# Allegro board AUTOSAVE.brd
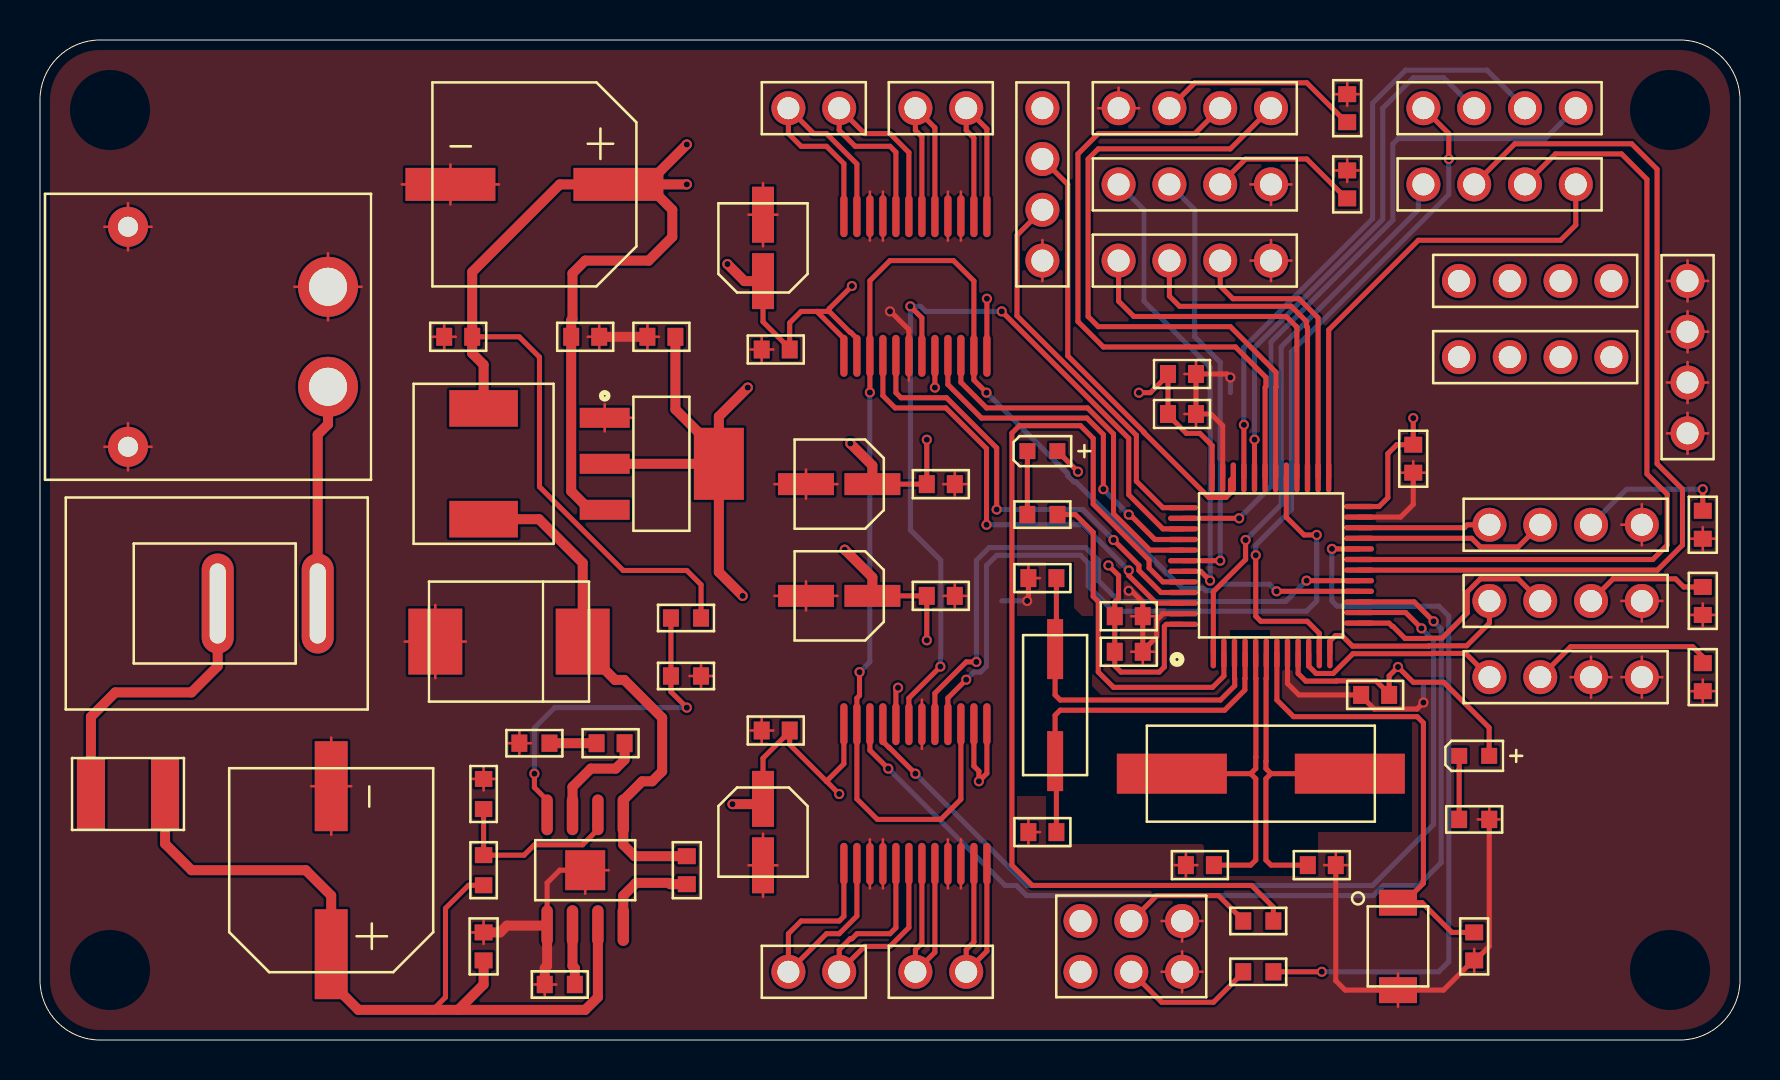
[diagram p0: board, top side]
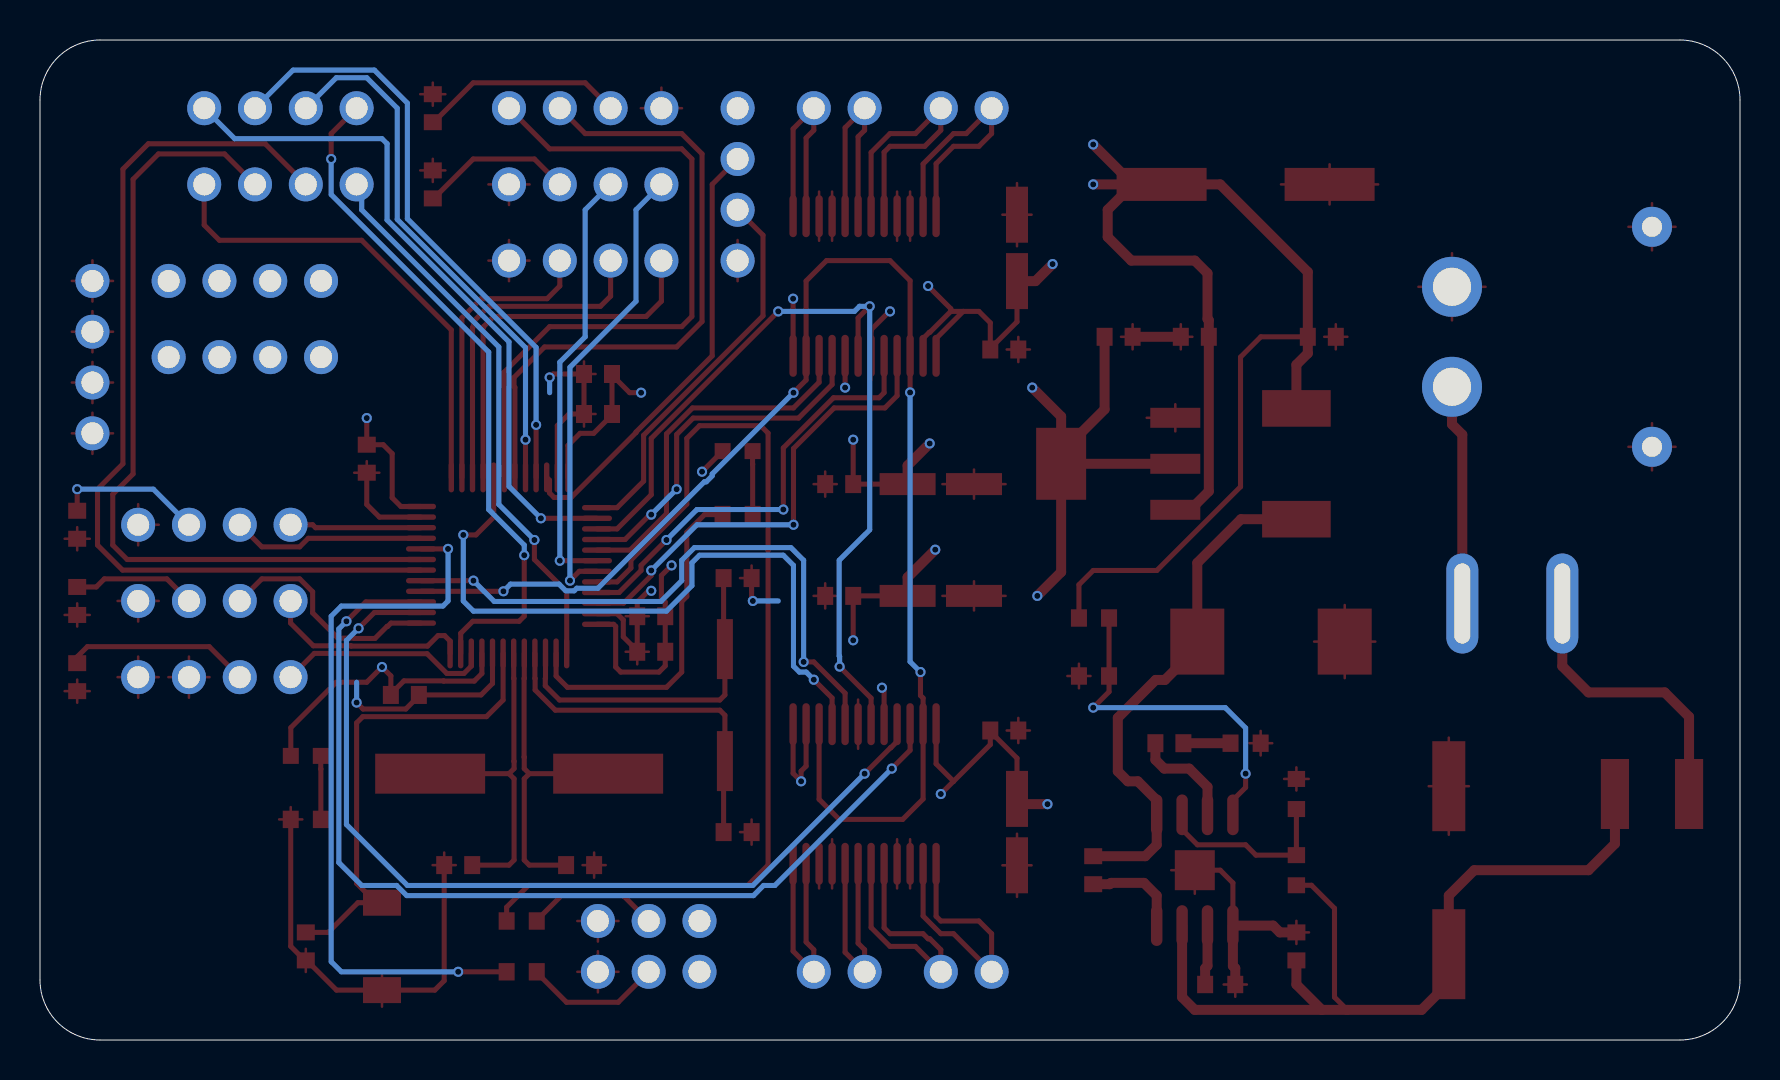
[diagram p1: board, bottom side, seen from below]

Outline 85 x 50 mm; copper layers: TOP, GND, POWER, BOTTOM. Coordinates in mm from the lower left corner of the outline.
Outline path: 0,47 0,3 arc(0.88,0.88) 3,0 82,0 arc(84.12,0.88) 85,3 85,47 arc(84.12,49.12) 82,50 3,50 arc(0.88,49.12) 0,47

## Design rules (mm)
constraint set DEFAULT: min track width 0.127
net group DP1_8MHZ: nets OSC_IN OSC_OUT
net group DP1_32KHZ: nets PC14 PC15

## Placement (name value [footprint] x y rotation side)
C1  22pF,16V  [C0603]  50.12 23.09 0 top
C2  22pF,16V  [C0603]  50.12 10.39 0 top
C3  22pF,16V  [C0603]  57.99 8.74 0 top
C4  22pF,16V  [C0603]  64.09 8.74 180 top
C5  4.7uF,16V  [C0603]  57.1 33.3 180 top
C6  100nF,16V  [C0603]  54.44 19.41 180 top
C7  100nF,16V  [C0603]  71.71 4.68 90 top
C8  100nF,16V  [C0603]  57.1 31.3 180 top
C9  10nF,16V  [C0603]  54.44 21.19 180 top
C10  1uF,16V  [C0603]  66.76 17.25 0 top
C11  100nF,16V  [C0603]  68.66 29.06 90 top
C12  100uF,50V  [C0603]  32.34 8.49 270 top
C13  220uF, 50V  [CP_D10XL10R2]  14.56 8.49 90 top
C14  10uF,50V  [C0603]  22.18 4.68 270 top
C15  22uF,50V  [C0603]  20.91 35.16 180 top
C16  220uF, 50V  [CP_D10XL10R2]  24.72 42.78 180 top
C17  150pF,50V  [C0603]  28.53 14.84 180 top
C18  4.7uF,50V  [C0603]  31.07 35.16 180 top
C19  1uF,50V  [C0603]  27.26 35.16 180 top
C20  100nF,16V  [C0603]  36.78 34.52 0 top
C21  100nF,16V  [C0603]  45.04 27.79 180 top
C22  10uF, 16V  [CP_D4XL54]  36.15 39.61 90 top
C23  10uF, 16V  [CP_D4XL54]  39.96 27.79 180 top
C24  100nF,16V  [C0603]  36.78 15.47 0 top
C25  100nF,16V  [C0603]  45.04 22.21 180 top
C26  10uF, 16V  [CP_D4XL54]  36.15 10.39 270 top
C27  10uF, 16V  [CP_D4XL54]  39.96 22.21 180 top
C28  100nF,16V  [C0603]  65.36 46.59 270 top
C29  100nF,16V  [C0603]  83.14 18.14 90 top
C30  100nF,16V  [C0603]  83.14 21.95 90 top
C31  100nF,16V  [C0603]  65.36 42.78 270 top
C32  100nF,16V  [C0603]  83.14 25.76 90 top
D1  LED  [LED0603]  71.71 14.21 0 top
D2  LED  [LED0603]  50.12 29.45 0 top
D3  SS34  [DO214AB]  23.45 19.92 180 top
F1  SMD1812-150-33 (3A)  [SMD1812]  4.4 12.3 0 top
J1  HEADER 4  [HDR4_P254]  50.12 42.78 90 top
J2  HEADER 3X2  [HDR3X2_P254]  54.56 4.68 0 top
J3  HEADER 4  [HDR4_P254]  72.98 46.59 0 top
J4  HEADER 4  [HDR4_P254]  72.98 42.78 0 top
J5  HDR_3V3  [HDR4_P254]  74.76 37.95 0 top
J6  HDR_5V  [HDR4_P254]  74.76 34.14 0 top
J7  HDR_GND  [HDR4_P254]  82.38 34.14 270 top
J8  HEADER 2  [HDR2_P254]  45.04 46.59 180 top
J9  HEADER 2  [HDR2_P254]  38.69 46.59 180 top
J10  HEADER 2  [HDR2_P254]  38.69 3.41 0 top
J11  HEADER 2  [HDR2_P254]  45.04 3.41 0 top
J12  HDR_USART1  [HDR4_P254]  57.74 46.59 180 top
J13  HDR_USART2  [HDR4_P254]  76.28 21.95 0 top
J14  HDR_SERVO  [HDR4_P254]  76.28 18.14 0 top
J15  HDR_I2C1  [HDR4_P254]  57.74 42.78 180 top
J16  HDR_I2C2  [HDR4_P254]  76.28 25.76 180 top
J17  HDR_SPI2  [HDR4_P254]  57.74 38.97 0 top
L1  10uH,3A  [H0630]  22.18 28.81 90 top
R1  10K  [R0603]  60.91 3.41 180 top
R2  10K  [R0603]  60.91 5.95 0 top
R3  510R  [R0603]  71.71 11.03 0 top
R4  510R  [R0603]  50.12 26.27 0 top
R5  100K  [R0603]  22.18 8.49 270 top
R6  100K  [R0603]  22.18 12.3 270 top
R7  100K  [R0603]  25.99 2.77 0 top
R8  210K 1%  [R0603]  32.3 21.1 180 top
R9  100K  [R0603]  24.72 14.84 0 top
R10  40R2K 1%  [R0603]  32.3 18.2 0 top
SW1  SW_PB_SPST  [SW_PB_4X3]  67.9 4.68 90 top
SW2  -  [KCD11-2P]  11.39 21.82 180 top
U1  STM32F103C8T6  [LQFP_48]  61.55 23.73 0 top
U2  -  [XT30]  4.4 35.16 90 top
U3  MP1584EN  [SOIC-8-EP]  27.26 8.49 180 top
U4  LDL1117_33R  [SOT223]  31.07 28.81 180 top
U5  TB6612FNG  [SSOP24]  43.77 37.7 180 top
U6  TB6612FNG  [SSOP24]  43.77 12.3 0 top
Y1  32.768kHz  [SMD_32KHZ]  50.76 16.74 90 top
Y2  8MHz  [SMD_8MHZ]  61.04 13.32 180 top

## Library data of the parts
C1-C12 C14 C15 C17-C21 C24 C25 C28-C32 = CAP NP
C13 C16 C22 C23 C26 C27 = CAP POL
D1 D2 = LED
D3 = DIODE
F1 = FUSE
J1 J3-J7 J12-J17 = HEADER 4
J2 = HEADER 3X2
J8-J11 = HEADER 2
L1 = INDUCTOR
R1-R10 = R2
SW1 = SW_PB_SPST
SW2 = SW SPST
U1 = STM32F103C8T6
U2 = XT30
U3 = MP1584EN
U4 = LDL1117_33R
U5 U6 = TB6612FNG
Y1 Y2 = CRYSTAL

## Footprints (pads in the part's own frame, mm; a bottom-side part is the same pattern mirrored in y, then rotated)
C0603
  rect 0.8x0.9 smd: 1(-0.7,0) 2(0.7,0)
CP_D4XL54
  rect 2.8x1.1 smd: 1(-1.66,0) 2(1.66,0)
CP_D10XL10R2
  rect 4.5x1.65 smd: 1(-4.2,0) 2(4.2,0)
DO214AB
  rect 2.7x3.3 smd: 1(-3.686,0) 2(3.686,0)
H0630
  rect 1.83x3.43 smd: 1(-2.77,0) 2(2.77,0)
HDR2_P254
  round 1.7 hole 1.1: 1(-1.27,0) 2(1.27,0)
HDR3X2_P254
  round 1.7 hole 1.1: 1(-2.54,1.27) 2(-2.54,-1.27) 3(0,1.27) 4(0,-1.27) 5(2.54,1.27) 6(2.54,-1.27)
HDR4_P254
  round 1.7 hole 1.1: 1(-3.81,0) 2(-1.27,0) 3(1.27,0) 4(3.81,0)
KCD11-2P
  oval 1.6x5 hole 0.8x4 unplated: (-2.5,0) (2.5,0)
LED0603
  rect 0.8x0.8 smd: 1(-0.749,0) 2(0.749,0)
LQFP_48
  oval 0.27x1.5 smd: 1(-2.885,-4.4) 2(-2.355,-4.4) 3(-1.825,-4.4) 4(-1.295,-4.4) 5(-0.765,-4.4) 6(-0.235,-4.4) 7(0.295,-4.4) 8(0.825,-4.4) 9(1.355,-4.4) 10(1.885,-4.4) 11(2.415,-4.4) 12(2.945,-4.4) 25(2.885,4.4) 26(2.355,4.4) 27(1.825,4.4) 28(1.295,4.4) 29(0.765,4.4) 30(0.235,4.4) 31(-0.295,4.4) 32(-0.825,4.4) 33(-1.355,4.4) 34(-1.885,4.4) 35(-2.415,4.4) 36(-2.945,4.4)
  oval 1.5x0.27 smd: 13(4.4,-2.885) 14(4.4,-2.355) 15(4.4,-1.825) 16(4.4,-1.295) 17(4.4,-0.765) 18(4.4,-0.235) 19(4.4,0.295) 20(4.4,0.825) 21(4.4,1.355) 22(4.4,1.885) 23(4.4,2.415) 24(4.4,2.945) 37(-4.4,2.885) 38(-4.4,2.355) 39(-4.4,1.825) 40(-4.4,1.295) 41(-4.4,0.765) 42(-4.4,0.235) 43(-4.4,-0.295) 44(-4.4,-0.825) 45(-4.4,-1.355) 46(-4.4,-1.885) 47(-4.4,-2.415) 48(-4.4,-2.945)
R0603
  rect 0.8x0.87 smd: 1(-0.753,0) 2(0.753,0)
SMD1812
  rect 1.407x3.499 smd: 1(-1.853,0) 2(1.853,0)
SMD_8MHZ
  rect 5.5x2 smd: 1(-4.45,0) 2(4.45,0)
SMD_32KHZ
  rect 3x0.8 smd: 1(-2.8,0) 2(2.8,0)
SOIC-8-EP
  oval 0.574x2.038 smd: 1(-1.905,-2.769) 2(-0.635,-2.769) 3(0.635,-2.769) 4(1.905,-2.769) 5(1.905,2.769) 6(0.635,2.769) 7(-0.635,2.769) 8(-1.905,2.769)
  rect 2x2 smd: 9(0,0)
SOT223
  rect 2.5x1 smd: 1(2.835,-2.3) 2(2.835,0) 3(2.835,2.3)
  rect 2.5x3.6 smd: 4(-2.873,0)
SSOP24
  oval 0.37x2.1 smd: 1(-3.575,-3.491) 2(-2.925,-3.491) 3(-2.275,-3.491) 4(-1.625,-3.491) 5(-0.975,-3.491) 6(-0.325,-3.491) 7(0.325,-3.491) 8(0.975,-3.491) 9(1.625,-3.491) 10(2.275,-3.491) 11(2.925,-3.491) 12(3.575,-3.491) 13(3.575,3.491) 14(2.925,3.491) 15(2.275,3.491) 16(1.625,3.491) 17(0.975,3.491) 18(0.325,3.491) 19(-0.325,3.491) 20(-0.975,3.491) 21(-1.625,3.491) 22(-2.275,3.491) 23(-2.925,3.491) 24(-3.575,3.491)
SW_PB_4X3
  rect 1.3x1.9 smd: 1(-2.185,0) 2(2.185,0)
XT30
  round 3 hole 1.9: 1(2.5,-10) 2(-2.5,-10)
  round 2 hole 1: 3(5.5,0) 4(-5.5,0)

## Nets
GND: C1.1 C2.1 C3.1 C4.1 C5.1 C6.1 C7.1 C8.1 C9.1 C10.1 C11.1 C13.2 C14.1 C15.2 C16.2 C18.2 C19.1 C20.1 C21.1 C22.2 C23.2 C24.1 C25.1 C26.2 C27.2 C28.1 C29.1 C30.1 C31.1 C32.1 D3.2 J1.1 J2.5 J2.6 J7.1 J7.2 J7.3 J7.4 J12.4 J13.4 J14.3 J14.4 J15.1 J16.1 J17.4 R3.2 R6.1 R7.1 R9.1 R10.2 SW1.1 U1.8 U1.23 U1.35 U1.47(VSS_3) U2.1 U2.3 U2.4 U3.5 U3.9 U4.1 U5.3 U5.4 U5.9 U5.10 U5.18 U6.3 U6.4 U6.9 U6.10 U6.18
VBAT: J4.1 U1.1
VCC3V3: C5.2 C6.2 C8.2 C9.2 C10.2 C11.2 C18.1 C30.2 C31.2 C32.2 D1.2 D2.2 J1.4 J2.1 J2.2 J5.1 J5.2 J5.3 J5.4 J13.3 J15.2 J16.2 U1.9 U1.24 U1.36 U1.48 U4.2 U4.4(VOUT2)
VCC5V: C15.1 C16.1 C19.2 C20.2 C21.2 C22.1 C23.1 C24.2 C25.2 C26.1 C27.1 C28.2 C29.2 J6.1 J6.2 J6.3 J6.4 J12.3 J14.2 L1.2 R8.1 U4.3 U5.13 U5.14(VM3) U5.20 U5.24 U6.13 U6.14(VM3) U6.20 U6.24
VIN_BAT: C13.1 C14.2 F1.2 R5.2 U3.7(VIN)
BOOT0: R2.2 U1.44
BOOT1: R1.1 U1.20
I2C1_SCL: J15.3 U1.42
I2C1_SDA: J15.4 U1.43
I2C2_SCL: J16.3 U1.21
I2C2_SDA: J16.4 U1.22
MOTORIC1_AIN1: U1.40 U5.21
MOTORIC1_AIN2: U1.41 U5.22
MOTORIC1_BIN1: U1.45 U5.17
MOTORIC1_BIN2: U1.46 U5.16
MOTORIC2_AIN1: U1.14 U6.21
MOTORIC2_AIN2: U1.15 U6.22
MOTORIC2_BIN1: U1.17 U6.17
MOTORIC2_BIN2: U1.29 U6.16
MOTORIC_STBY: U1.39 U5.19 U6.19
OSC_IN: C3.2 U1.5 Y2.2
OSC_OUT: C4.2 U1.6 Y2.1
PA1: J3.1 U1.11
PA11: J3.2 U1.32
PA12: J3.3 U1.33
PA15: J3.4 U1.38
PB0: J4.2 U1.18
PB1: J4.3 U1.19
PB12: J4.4 U1.25
PC13: R4.2 U1.2
PC14: C1.2 U1.3 Y1.2
PC15: C2.2 U1.4 Y1.1
RESET: C7.2 SW1.2 U1.7
SPI2_MISO: J17.2 U1.27
SPI2_MOSI: J17.1 U1.28
SPI2_SCK: J17.3 U1.26
SWCLK: J1.2 U1.37
SWDIO: J1.3 U1.34
TIM2_PWM: J14.1 U1.10
TIM3_PWM: U1.16 U5.15 U5.23 U6.15 U6.23
USART1_RX: J12.2 U1.31
USART1_TX: J12.1 U1.30
USART2_RX: J13.2 U1.13
USART2_TX: J13.1 U1.12
N13546: J8.1 U5.1 U5.2
N13563: J8.2 U5.5 U5.6
N13598: J9.1 U5.7 U5.8
N13619: J9.2 U5.11 U5.12
N15223: J10.1 U6.1 U6.2
N15263: J10.2 U6.5 U6.6
N15407: J11.1 U6.7 U6.8
N15519: J11.2 U6.11 U6.12
N31972: C12.2 U3.8
N31979: C12.1 D3.1(K) L1.1 U3.1
N32592: R7.2 U3.6
N32821: R5.1 R6.2 U3.2
N35796: C17.1 U3.3
N36210: C17.2 R9.2
N38494: R8.2 R10.1 U3.4
N053341: J2.4 R1.2
N053344: J2.3 R2.1
N066431: D1.1(CATHODE) R3.1
N066591: D2.1(CATHODE) R4.1
N113201: U2.2
N288331: F1.1

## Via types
v1: diameter 0.508, hole 0.305, TOP to BOTTOM, 60 vias

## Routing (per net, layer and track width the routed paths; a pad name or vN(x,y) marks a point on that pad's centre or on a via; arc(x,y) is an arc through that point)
GND: length 334.8
  TOP w0.127: 82.38,34.39 J7.2 ; J7.2 83.41,35.41 ; J7.2 82.38,36.44 ; J7.2 81.35,35.41 ; 68.03,28.36 C11.1 ; C11.1 69.29,28.36 ; C11.1 68.66,28.94 ; 45.74,21.58 C25.1 ; C25.1 46.32,22.21 ; C25.1 45.74,22.83 ; C25.1 45.16,22.21 ; 22.18,4.8 C14.1 ; C14.1 22.18,5.96 ; C14.1 21.55,5.38 ; U4.1 28.23,31.79 ; U4.1 28.23,30.43 ; U4.1 29.66,31.11 ; U2.1 16.08,37.66 ; U2.1 14.4,35.98 ; U2.1 14.4,39.34 ; U2.1 12.72,37.66 ; 41.49,42.42 U5.10 41.49,39.96 ; C4.1 64.79,9.37 ; C4.1 65.37,8.74 ; C4.1 64.21,8.74 ; 80.09,17.11 J14.4 ; J14.4 81.12,18.14 ; J14.4 80.09,19.17 ; J14.4 79.06,18.14 ; 27.96,34.53 C19.1 ; C19.1 27.96,35.79 ; C19.1 27.38,35.16 ; 43.45,32.98 U5.18 ; 45.16,27.79 C21.1 ; C21.1 45.74,28.42 ; C21.1 45.74,27.17 ; C21.1 46.32,27.79 ; J17.4 61.55,40 ; J17.4 62.58,38.97 ; J17.4 61.55,37.94 ; J17.4 60.52,38.97 ; C22.2 36.88,41.27 ; C22.2 36.15,42.84 ; C22.2 36.15,39.69 ; C22.2 35.42,41.27 ; 57.8,30.67 C8.1 57.22,31.3 ; C32.1 83.77,25.06 ; C32.1 83.14,24.48 ; C32.1 82.51,25.06 ; C32.1 83.14,25.64 ; 56.72,8.74 C3.1 ; C3.1 57.29,8.12 ; C3.1 57.29,9.37 ; C3.1 57.87,8.74 ; 4.4,28.48 U2.4 ; U2.4 5.58,29.66 ; U2.4 4.4,30.84 ; U2.4 3.22,29.66 ; 4.4,39.48 U2.3 ; U2.3 5.58,40.66 ; U2.3 3.22,40.66 ; U2.3 4.4,41.84 ; C29.1 83.77,17.44 ; C29.1 82.51,17.44 ; C29.1 83.14,16.86 ; C29.1 83.14,18.02 ; 41.49,10.04 U6.3 41.49,7.58 ; 25.24,2.16 R7.1 ; R7.1 25.82,2.77 ; R7.1 24.66,2.77 ; C18.2 30.37,35.79 ; C18.2 30.37,34.53 ; C18.2 30.95,35.16 ; 32.48,18.2 R10.2 ; R10.2 33.05,18.81 ; R10.2 33.63,18.2 ; R10.2 33.05,17.59 ; 42.15,39.96 42.15,42.42 ; 56.08,5.95 J2.5 ; J2.5 58.13,5.95 ; J2.5 57.11,4.92 ; 81.35,37.95 J7.1 ; J7.1 82.38,36.93 ; J7.1 83.41,37.95 ; J7.1 82.38,38.98 ; 42.15,10.04 U6.4 42.15,7.58 ; 60.52,42.78 J15.1 ; J15.1 61.55,41.75 ; J15.1 62.58,42.78 ; 35.42,8.73 C26.2 ; C26.2 36.15,7.16 ; C26.2 36.88,8.73 ; C26.2 36.15,10.31 ; 81.35,32.87 J7.3 ; J7.3 83.41,32.87 ; J7.3 82.38,31.85 ; J7.3 82.38,33.9 ; 79.06,21.95 J13.4 ; J13.4 81.12,21.95 ; J13.4 80.09,20.92 ; C13.2 15.56,12.69 ; C13.2 14.56,10.26 ; C13.2 13.56,12.69 ; C13.2 14.56,15.12 ; 64.73,43.48 C31.1 ; C31.1 65.36,44.06 ; C31.1 65.36,42.9 ; C31.1 65.99,43.48 ; 35.51,15.47 C24.1 ; C24.1 36.66,15.47 ; C24.1 36.09,14.85 ; C24.1 36.09,16.1 ; J16.1 80.09,26.79 ; J16.1 80.09,24.73 ; J16.1 79.06,25.76 ; R6.1 22.18,13.63 ; R6.1 22.18,12.47 ; R6.1 22.79,13.05 ; R6.1 21.57,13.05 ; 49.42,23.72 C1.1 50,23.09 ; 45.4,39.96 U5.4 45.4,42.42 ; 55.72,21.19 C9.1 54.56,21.19 ; C15.2 20.21,35.79 ; C15.2 19.63,35.16 ; C15.2 20.79,35.16 ; C15.2 20.21,34.53 ; 57.8,33.93 C5.1 57.22,33.3 ; 52.9,46.59 J12.4 ; J12.4 53.93,47.62 ; J12.4 54.96,46.59 ; C6.1 55.72,19.41 ; C6.1 55.14,18.78 ; C6.1 54.56,19.41 ; J7.4 83.41,30.33 ; J7.4 81.35,30.33 ; J7.4 82.38,29.31 ; J7.4 82.38,31.36 ; 83.14,20.67 C30.1 ; C30.1 83.77,21.25 ; C30.1 83.14,21.83 ; C30.1 82.51,21.25 ; 36.72,27.79 C23.2 ; C23.2 38.3,27.07 ; C23.2 39.88,27.79 ; C23.2 38.3,28.52 ; R9.1 24.55,14.84 ; R9.1 23.39,14.84 ; R9.1 23.97,15.45 ; R9.1 23.97,14.23 ; R3.2 72.46,11.64 ; R3.2 71.89,11.03 ; R3.2 73.04,11.03 ; C2.1 50,10.39 ; C2.1 49.42,9.77 ; C2.1 49.42,11.02 ; 50.12,40 J1.1 50.12,37.94 ; 46.05,7.58 U6.10 46.05,10.04 ; C20.1 36.09,35.15 ; C20.1 35.51,34.52 ; C20.1 36.66,34.52 ; C20.1 36.09,33.9 ; 77.55,17.11 J14.3 ; J14.3 77.55,19.17 ; J14.3 76.52,18.14 ; J14.3 78.58,18.14 ; 46.05,42.42 46.05,39.96 ; 45.4,10.04 U6.9 45.4,7.58 ; 67.9,3.32 SW1.1 67.9,1.67 ; 71.71,3.4 C7.1 71.71,4.56 ; 57.11,2.38 J2.6 ; J2.6 57.11,4.44 ; J2.6 56.08,3.41 ; J2.6 58.13,3.41 ; 18.09,42.78 C16.2 ; C16.2 20.52,43.78 ; C16.2 20.52,41.78 ; C16.2 22.95,42.78 ; 64.73,47.29 C28.1 ; C28.1 65.36,47.87 ; C28.1 65.99,47.29 ; C28.1 65.36,46.71 ; 44.09,14.56 U6.18 44.09,17.02 ; 27.26,7.31 U3.9 28.44,8.49 ; 18.24,19.92 D3.2 ; D3.2 19.76,18.09 ; D3.2 19.76,21.75 ; D3.2 21.29,19.92 ; C27.2 38.3,22.93 ; C27.2 39.88,22.21 ; C27.2 38.3,21.48 ; C27.2 36.72,22.21
  TOP w0.254: v1(42.5,36.43) 42.53,36.43 43.45,35.51 U5.18 ; U1.23 68.03,26.14 68.66,26.78 C11.1 ; v1(49.36,21.95) 49.42,22.01 C1.1 ; U3.9 25.99,8.49 25.36,7.86 U3.5 ; 55.14,19.46 55.84,20.16 55.84,21 56.15,21.32 U1.47 ; 55.14,19.46 C6.1 ; 55.14,19.46 C9.1 55.14,21.89 54.57,22.46 v1(54.44,22.46) ; v1(69.17,16.87) 68.85,16.55 66.71,16.55 66.06,17.2 66.06,17.25 62.95,17.25 62.38,17.82 U1.8 ; R3.2 72.46,4.68 71.76,3.98 C7.1 71.66,3.98 70.17,2.5 SW1.1 65.26,2.5 64.79,2.96 C4.1 ; U1.35 59.14,30.72 58.55,31.3 C8.1 C5.1 59.35,33.3 v1(59.52,33.13)
  TOP w0.5: R7.1 25.24,3.59 25.36,3.7 U3.5 23.35,5.72 23.01,5.38 C14.1 ; C19.1 C18.2
  GND w0.127: 81.35,30.33 J7.4 ; J7.4 83.41,30.33 ; J7.4 82.38,29.31 ; J7.4 82.38,31.36 ; 4.4,39.48 U2.3 ; U2.3 3.22,40.66 ; U2.3 4.4,41.84 ; U2.3 5.58,40.66 ; 81.35,35.41 J7.2 ; J7.2 82.38,36.44 ; J7.2 83.41,35.41 ; J7.2 82.38,34.39 ; U2.4 4.4,30.84 ; U2.4 4.4,28.48 ; U2.4 3.22,29.66 ; U2.4 5.58,29.66 ; J7.3 82.38,33.9 ; J7.3 83.41,32.87 ; J7.3 82.38,31.85 ; J7.3 81.35,32.87 ; J12.4 54.96,46.59 ; J12.4 52.9,46.59 ; J12.4 53.93,45.56 ; J12.4 53.93,47.62 ; 14.4,35.98 U2.1 ; U2.1 14.4,39.34 ; U2.1 12.72,37.66 ; U2.1 16.08,37.66 ; 49.09,38.97 J1.1 ; J1.1 50.12,37.94 ; J1.1 50.12,40 ; J1.1 51.15,38.97 ; J2.6 58.13,3.41 ; J2.6 57.11,4.44 ; J2.6 56.08,3.41 ; J2.6 57.11,2.38 ; 56.08,5.95 J2.5 ; J2.5 58.13,5.95 ; J2.5 57.11,4.92 ; J2.5 57.11,6.98 ; 76.52,18.14 J14.3 ; J14.3 77.55,19.17 ; J14.3 78.58,18.14 ; J14.3 77.55,17.11 ; J7.1 83.41,37.95 ; J7.1 82.38,38.98 ; J7.1 82.38,36.93 ; J7.1 81.35,37.95 ; 61.55,41.75 J15.1 ; J15.1 62.58,42.78 ; J15.1 61.55,43.81 ; J15.1 60.52,42.78 ; 60.52,38.97 J17.4 ; J17.4 61.55,37.94 ; J17.4 61.55,40 ; J17.4 62.58,38.97 ; J14.4 80.09,19.17 ; J14.4 79.06,18.14 ; J14.4 80.09,17.11 ; J14.4 81.12,18.14 ; 79.06,25.76 J16.1 ; J16.1 80.09,26.79 ; J16.1 80.09,24.73 ; J16.1 81.12,25.76 ; 80.09,20.92 J13.4 ; J13.4 80.09,22.98 ; J13.4 79.06,21.95 ; J13.4 81.12,21.95
  GND w0.254: v1(42.5,36.43) 42.5,37.19
  BOTTOM w0.254: v1(49.36,21.95) 48.09,21.95 ; v1(59.52,33.13) 59.52,32.37 ; v1(69.17,16.87) 69.17,17.89
VBAT: length 27.8
  TOP w0.254: v1(60.28,25) 60.28,24.03 58.66,22.41 U1.1
  BOTTOM w0.254: J4.1 68.92,42.53 68.92,41.51 62.06,34.65 62.06,26.78 v1(60.28,25)
VCC3V3: length 256.2
  TOP w0.254: D2.2 v1(51.9,28.42) ; U1.48 56.32,20.79 56.22,20.68 56.22,18.65 55.96,18.4 54.05,18.4 53.74,18.71 C6.2 C9.2 53.74,21.89 53.93,22.09 53.93,23.22 v1(53.42,23.73) ; v1(54.95,32.37) 55.52,32.37 56.4,33.25 ; C10.2 67.46,17.3 ; 67.46,17.3 67.46,18.21 v1(67.9,18.65) 68.66,17.89 70.19,17.89 72.46,15.62 D1.2 ; 67.46,17.3 66.8,17.96 64.83,17.96 64.81,17.95 63.29,17.95 62.91,18.33 U1.9 ; 56.4,33.25 C5.2 ; 56.4,33.25 C8.2 56.4,31.25 57.32,30.33 57.99,30.33 58.61,29.72 U1.36 ; C32.2 v1(83.14,27.54) ; v1(68.66,31.1) C11.2 67.84,29.76 67.39,29.32 67.39,27.11 66.95,26.68 65.95,26.68 ; J13.3 78.66,23.06 81.78,23.06 82.19,22.65 C30.2 ; C31.2 65.31,42.08 63.34,44.05 60.28,44.05 J15.2
  TOP w0.5: v1(35.39,32.62) 33.94,31.18 33.94,29.36 ; U4.2 U4.4 ; U4.4 33.94,29.36 ; U4.4 33.94,23.4 v1(35.13,22.21) ; 33.94,29.36 31.77,31.53 C18.1
  POWER w0.254: 54.18,33.89 54.95,33.13 v1(54.95,32.37) ; 49.87,33.89 51.9,31.86 v1(51.9,28.42) ; 66.63,33.89 68.66,31.86 v1(68.66,31.1)
  POWER w0.5: J5.4 J5.3 J5.2 J5.1 66.88,33.89 ; 49.1,33.89 51.64,36.43 51.64,45.07 J1.4 ; 49.1,33.89 36.66,33.89 v1(35.39,32.62) ; 49.1,33.89 62.31,33.89 ; 66.88,33.89 68.41,33.89 70.44,31.86 76.28,31.86 77.55,30.59 J16.2 J13.3 75.77,20.17 72.22,20.17 70.69,18.65 v1(67.9,18.65) ; 66.88,33.89 62.31,33.89 ; 62.31,33.89 63.84,35.41 63.84,40.24 63.33,40.75 61.04,40.75 J15.2 ; v1(53.42,23.73) 52.15,25 42.68,25 41.03,23.35 36.28,23.35 v1(35.13,22.21) 38.44,18.9 38.44,7.73 39.2,6.97 51.01,6.97 J2.1 J2.2
  BOTTOM w0.254: J16.2 79.33,27.54 v1(83.14,27.54)
VCC5V: length 312.6
  TOP w0.254: 38.84,36.43 38.05,36.43 37.48,35.86 37.48,34.58 ; 38.84,36.43 40.2,35.07 40.2,34.21 ; 38.84,36.43 39.46,36.43 ; 37.48,15.43 37.48,14.77 39.32,12.94 ; 37.48,15.43 C24.2 ; 37.48,15.43 36.15,14.09 C26.1 ; v1(44.34,30.02) C21.2 C23.1 ; U6.20 42.8,17.51 v1(42.9,17.61) ; C22.1 36.15,35.91 37.48,34.58 ; J14.2 76.54,19.67 82.63,19.67 83.14,19.16 C29.2 ; U5.14 40.84,35.07 40.53,35.38 40.51,35.38 39.46,36.43 ; 39.32,12.94 39.33,12.94 v1(39.96,12.3) ; 39.32,12.94 40.2,13.81 U6.24 ; C15.1 23.96,35.16 24.97,34.14 24.97,27.66 29.16,23.48 32.34,23.48 33.05,22.76 R8.1 ; C28.2 65.31,45.89 63.34,47.86 57.74,47.86 J12.3 ; v1(44.74,32.62) U5.20 ; v1(47.34,37.06) 47.34,34.21 ; U6.14 46.7,13.69 46.95,13.44 v1(46.95,12.94) 47.34,13.34 47.34,15.79 ; v1(44.34,19.98) C25.2 C27.1 ; 37.48,34.58 C20.2 ; 39.46,36.43 39.46,36.56 v1(40.59,37.7)
  TOP w0.5: U4.3 27.48,26.51 26.56,27.43 C19.2 26.56,35.99 26.62,36.05 26.62,38.34 27.26,38.97 30.44,38.97 31.62,40.15 31.62,41.51 30.34,42.78 ; 30.34,42.78 v1(32.34,42.78) ; 30.34,42.78 v1(32.34,44.77) ; 30.34,42.78 C16.1 25.99,42.78 21.61,38.4 C15.1 21.61,34.33 22.18,33.76 L1.2 ; C23.1 41.62,28.72 v1(40.52,29.83) ; v1(34.37,38.8) 35.22,37.95 C22.1 ; C27.1 41.62,23.13 v1(40.24,24.52) ; v1(34.63,11.79) 35.89,11.79 C26.1
  POWER w0.254: v1(46.95,12.94) 46.31,12.3 v1(39.96,12.3) ; v1(47.34,37.06) 46.71,37.7 v1(40.59,37.7) ; v1(44.74,32.62) 44.34,32.22 v1(44.34,30.02) ; v1(42.9,17.61) 44.34,19.05 v1(44.34,19.98)
  POWER w0.5: v1(34.37,38.8) 34.29,38.8 33.36,39.73 ; 33.36,26.02 34.86,24.52 v1(40.24,24.52) ; 33.36,26.02 33.36,32.37 ; 33.36,26.02 33.36,13.06 v1(34.63,11.79) ; 79.84,35.41 79.84,30.59 81.87,28.56 81.87,16.87 80.85,15.86 77.3,15.86 J14.2 ; 79.84,35.41 J6.4 J6.3 J6.2 J6.1 ; 79.84,35.41 80.09,35.67 80.09,39.99 78.82,41.26 78.82,46.84 77.3,48.37 54.7,48.37 ; 33.36,32.37 35.9,29.83 v1(40.52,29.83) ; 33.36,32.37 33.36,39.73 ; v1(32.34,44.77) 35.93,48.37 54.7,48.37 ; 54.7,48.37 55.2,47.87 55.2,47.86 J12.3 ; v1(32.34,42.78) 33.36,41.76 33.36,39.73
VIN_BAT: length 44.7
  TOP w0.254: 19.64,1.5 20.27,2.14 20.27,6.59 21.43,7.74 R5.2
  TOP w0.5: 20.91,1.5 15.92,1.5 14.56,2.86 C13.1 14.56,7.22 13.29,8.49 7.58,8.49 6.25,9.81 F1.2 ; 20.91,1.5 27.26,1.5 27.89,2.14 U3.7 ; 20.91,1.5 22.18,2.77 C14.2
BOOT0: length 50.3
  TOP w0.254: R2.2 61.67,6.64 60.58,7.73 49.61,7.73 48.6,8.74 48.6,30.34 48.97,30.71 52.02,30.71 52.66,30.08 52.66,26.79 55.45,24 55.45,23.6 56.15,22.91 57.15,22.91
BOOT1: length 36.4
  TOP w0.254: R1.1 v1(64.09,3.41) ; v1(64.6,24.55) 65.95,24.55
  BOTTOM w0.254: v1(64.6,24.55) 64.6,21.95 64.85,21.7 69.93,21.7 70.44,21.19 70.44,3.92 69.93,3.41 v1(64.09,3.41)
I2C1_SCL: length 21.7
  TOP w0.254: U1.42 v1(59.01,23.96)
  BOTTOM w0.254: v1(59.01,23.96) 59.01,33.89 57.74,35.16 57.74,41.51 J15.3
I2C1_SDA: length 23.3
  TOP w0.254: U1.43 58.03,23.43 v1(58.5,22.97)
  BOTTOM w0.254: J15.4 55.2,41.51 55.2,36.94 58.5,33.64 v1(58.5,22.97)
I2C2_SCL: length 9.7
  TOP w0.254: U1.21 71.59,25.09 72.01,24.66 73.91,24.66 J16.3
I2C2_SDA: length 6.6
  TOP w0.254: U1.22 71.22,25.61 71.37,25.76 J16.4
MOTORIC1_AIN1: length 18
  TOP w0.254: 45.4,34.21 45.4,32.77 47.07,31.1 52.34,31.1 53.17,30.27 v1(53.17,27.54) ; v1(54.44,26.27) 54.56,26.14 54.63,26.14 55.74,25.02 U1.40
  BOTTOM w0.254: v1(53.17,27.54) v1(54.44,26.27)
MOTORIC1_AIN2: length 18.2
  TOP w0.254: U5.22 46.05,32.88 47.33,31.6 52.38,31.6 53.68,30.3 53.68,26.31 55.49,24.5 U1.41
MOTORIC1_BIN1: length 22.3
  TOP w0.254: v1(47.83,26.52) 47.83,29.6 45.32,32.11 43.05,32.11 42.8,32.37 42.8,34.21 ; U1.45 56.05,22.38 54.95,23.48 54.95,23.73 v1(53.68,25)
  BOTTOM w0.254: v1(47.83,26.52) 52.15,26.52 v1(53.68,25)
MOTORIC1_BIN2: length 23.7
  TOP w0.254: U5.16 42.15,32.21 42.75,31.6 45.29,31.6 47.33,29.57 v1(47.33,25.76) ; U1.46 55.81,21.84 54.44,23.22 v1(54.44,23.48)
  BOTTOM w0.254: v1(54.44,23.48) 52.15,25.76 v1(47.33,25.76)
MOTORIC2_AIN1: length 46.2
  TOP w0.254: v1(69.07,20.58) 68.28,21.38 U1.14 ; v1(43.77,13.32) 42.47,14.62 42.46,14.62 42.15,14.93 U6.21
  BOTTOM w0.254: v1(69.07,20.58) 69.68,19.98 69.68,10.78 66.63,7.73 49.36,7.73 v1(43.77,13.32)
MOTORIC2_AIN2: length 49.9
  TOP w0.254: 65.95,21.91 68.71,21.91 v1(69.68,20.94) ; v1(42.41,13.57) 41.49,14.49 U6.22
  BOTTOM w0.254: v1(69.68,20.94) 70.06,20.55 70.06,8.87 68.92,7.73 67.17,7.73 66.66,7.22 49.33,7.22 48.82,7.73 48.25,7.73 v1(42.41,13.57)
MOTORIC2_BIN1: length 30.9
  TOP w0.254: U6.17 44.74,17.34 46.31,18.9 v1(46.82,18.9) ; v1(63.33,22.97) 63.84,22.97 63.84,22.96 U1.17
  BOTTOM w0.254: v1(46.82,18.9) 46.82,23.98 47.45,24.62 52.28,24.62 52.91,23.98 52.91,22.97 53.96,21.93 62.29,21.93 v1(63.33,22.97)
MOTORIC2_BIN2: length 34.9
  TOP w0.254: v1(46.31,18.02) 45.4,17.1 U6.16 ; U1.29 62.31,26.14 63.2,25.25 v1(63.84,25.25)
  BOTTOM w0.254: v1(63.84,25.25) 63.84,21.95 63.33,21.44 53.68,21.44 52.41,22.71 52.41,23.86 52.02,24.24 47.83,24.24 47.33,23.73 47.33,18.69 47.03,18.4 46.69,18.4 v1(46.31,18.02)
MOTORIC_STBY: length 44.8
  TOP w0.254: 43.45,15.79 43.45,17.09 v1(45.02,18.67) ; v1(48.09,36.43) 54.44,30.08 54.44,27.26 56.15,25.55 57.15,25.55 ; v1(43.52,36.68) 44.09,36.11 44.09,34.21
  BOTTOM w0.254: v1(45.02,18.67) 45.02,19.18 45.04,19.2 45.04,23.98 43.52,25.51 v1(43.52,36.68) 44.02,36.68 44.28,36.43 v1(48.09,36.43)
OSC_IN: length 16.7
  TOP w0.254: 60.53,13.32 60.79,13.57 60.79,14.14 60.8,14.15 60.8,18.07 60.78,18.08 U1.5 ; 60.53,13.32 60.79,13.06 60.79,9 60.53,8.74 C3.2 ; 60.53,13.32 Y2.2
OSC_OUT: length 16.7
  TOP w0.254: 61.55,13.32 Y2.1 ; 61.55,13.32 61.3,13.06 61.3,9 61.55,8.74 C4.2 ; 61.55,13.32 61.3,13.57 61.3,13.93 61.3,13.94 61.3,18.07 61.31,18.08 U1.6
PA1: length 34.5
  TOP w0.254: v1(70.44,44.05) 70.44,45.32 J3.1 ; U1.11 63.97,20.33 63.36,20.94 61.04,20.94 60.79,21.19 v1(60.79,24.24)
  BOTTOM w0.254: v1(60.79,24.24) 60.79,24.75 62.57,26.52 62.57,34.4 70.44,42.27 v1(70.44,44.05)
PA11: length 27
  TOP w0.254: U1.32 v1(60.73,30.02)
  BOTTOM w0.254: v1(60.73,30.02) 60.73,34.62 67.14,41.03 67.14,46.59 68.66,48.11 70.19,48.11 J3.2
PA12: length 30.5
  TOP w0.254: U1.33 v1(60.2,30.76)
  BOTTOM w0.254: v1(60.2,30.76) 60.2,34.63 66.63,41.06 66.63,46.84 68.28,48.5 72.34,48.5 J3.3
PA15: length 34.6
  TOP w0.254: U1.38 v1(59.96,26.09)
  BOTTOM w0.254: J3.4 75.27,45.07 67.9,45.07 67.65,44.81 67.65,41 61.55,34.91 61.55,27.68 v1(59.96,26.09)
PB0: length 46.5
  TOP w0.254: J4.2 73.74,44.81 79.58,44.81 80.85,43.54 80.85,28.81 82.12,27.54 82.12,24.75 80.87,23.5 U1.18
PB1: length 41.7
  TOP w0.254: J4.3 75.77,44.3 79.08,44.3 80.35,43.03 80.35,28.3 81.36,27.29 81.36,24.75 80.64,24.02 U1.19
PB12: length 23.9
  TOP w0.254: U1.25 64.44,35.51 68.92,39.99 76.03,39.99 76.79,40.75 J4.4
PC13: length 17.2
  TOP w0.254: U1.2 59.2,18.2 58.63,17.63 53.68,17.63 52.91,18.4 52.91,21.92 52.66,22.18 52.66,25.38 51.77,26.27 R4.2
PC14: length 16.9
  TOP w0.254: C1.2 50.82,19.61 Y1.2 50.76,17.25 51.01,17 59.02,17 59.74,17.71 59.74,18.07 59.73,18.08 U1.3
PC15: length 17.7
  TOP w0.254: U1.4 60.25,18.08 60.24,18.07 60.24,17.5 59.23,16.49 51.01,16.49 50.76,16.24 Y1.1 50.82,13.88 C2.2
RESET: length 23.9
  TOP w0.254: 68.2,6.86 69.1,6.86 70.59,5.38 C7.2 ; 68.2,6.86 69.17,7.84 69.17,15.86 68.86,16.17 62.68,16.17 61.84,17 61.84,19.33 ; 68.2,6.86 SW1.2
SPI2_MISO: length 17
  TOP w0.254: J17.2 56.47,37.19 56.98,36.68 62.57,36.68 63.33,35.92 63.33,35.68 63.38,35.63 U1.27
SPI2_MOSI: length 19
  TOP w0.254: J17.1 53.93,36.94 54.69,36.18 62.31,36.18 62.82,35.67 62.82,35.66 62.84,35.63 U1.28
SPI2_SCK: length 14.8
  TOP w0.254: J17.3 59.01,37.7 59.64,37.06 62.95,37.06 63.91,36.11 U1.26
SWCLK: length 19.4
  TOP w0.254: J1.2 48.85,40.24 48.85,36.21 54.82,30.24 54.82,27.94 56.15,26.61 57.15,26.61
SWDIO: length 22.4
  TOP w0.254: U1.34 59.52,27.99 59.52,27.35 59.3,27.13 58.44,27.13 55.2,30.37 55.2,30.4 51.39,34.21 51.39,42.78 J1.3
TIM2_PWM: length 10.7
  TOP w0.254: U1.10 63.44,18.69 63.8,18.33 64.66,18.33 65.64,19.31 69.6,19.31 69.61,19.33 71.28,19.33 J14.1
TIM3_PWM: length 70.9
  TOP w0.254: v1(47.33,32.37) 46.7,33 U5.23 46.7,37.95 45.67,38.97 42.5,38.97 41.49,37.97 v1(41.49,32.38) ; v1(40.98,18.4) 40.98,17.23 40.84,17.09 40.84,12.05 41.87,11.03 45.04,11.03 46.05,12.04 U6.15 ; U1.16 v1(61.83,22.43)
  BOTTOM w0.254: v1(40.98,18.4) 41.49,18.91 v1(41.49,32.38) ; v1(61.83,22.43) 61.47,22.79 59.05,22.79 58.71,22.46 58.29,22.46 58.16,22.59 57.11,22.59 51.78,27.91 51.69,27.91 51.39,28.21 51.39,28.3 v1(47.33,32.37)
USART1_RX: length 32
  TOP w0.254: U1.31 61.25,32.63 61.3,32.67 61.3,33.13 59.77,34.65 53.17,34.65 51.9,35.92 51.9,44.3 52.91,45.32 57.74,45.32 J12.2
USART1_TX: length 33.9
  TOP w0.254: J12.1 59.52,44.56 52.91,44.56 52.41,44.05 52.41,36.18 52.91,35.67 59.52,35.67 61.8,33.38 61.8,32.65 61.78,32.63 U1.30
USART2_RX: length 11.7
  TOP w0.254: J13.2 73.91,23.06 72.01,23.06 71.37,22.41 71.37,21.36 70.1,20.09 69.3,20.09 69.28,20.08 68.25,20.08 67.65,20.68 67.61,20.68 67.45,20.84 65.95,20.84
USART2_TX: length 10.5
  TOP w0.254: U1.12 64.5,19.95 64.77,20.22 65.1,20.22 65.62,19.7 69.44,19.7 69.46,19.71 71.34,19.71 72.47,20.85 J13.1
N13546: length 11.4
  TOP w0.254: 47.34,41.19 47.34,45.55 J8.1 46.31,45.49 46.7,45.1 U5.2
N13563: length 11.3
  TOP w0.254: 44.74,41.19 44.74,45.61 J8.2 43.77,45.49 44.09,45.16 U5.6
N13598: length 15.2
  TOP w0.254: U5.8 42.8,44.39 42.5,44.69 40.76,44.69 39.96,45.49 J9.1 41.23,45.32 42.5,45.32 43.45,44.38 43.45,41.19
N13619: length 14.5
  TOP w0.254: U5.12 40.2,43.81 39.33,44.69 38.05,44.69 37.42,45.32 J9.2 38.69,45.32 39.33,45.32 40.84,43.8 40.84,41.19
N15223: length 14.9
  TOP w0.254: 40.84,8.81 40.84,6.2 39.96,5.32 39.33,5.32 J10.1 37.42,5.32 38.05,5.95 39.96,5.95 40.2,6.18 U6.1
N15263: length 15.2
  TOP w0.254: 43.45,8.81 43.45,5.62 42.5,4.68 41.23,4.68 J10.2 39.96,4.51 40.51,5.06 40.59,5.06 40.85,5.32 42.5,5.32 42.8,5.61 U6.5
N15407: length 11.3
  TOP w0.254: U6.8 44.74,4.39 J11.1 43.77,4.51 44.09,4.84 U6.7
N15519: length 11.4
  TOP w0.254: 47.34,8.81 47.34,4.45 J11.2 46.31,4.51 46.7,4.9 U6.11
N31972: length 5
  TOP w0.5: U3.8 29.16,7.22 29.8,7.86 31.45,7.86 31.51,7.79 C12.2
N31979: length 26.4
  TOP w0.5: L1.1 24.95,26.04 27.14,23.85 D3.1 27.14,19.62 28.75,18 29.22,18 31.11,16.11 31.11,13.44 30.61,12.94 30.11,12.94 29.16,11.99 29.16,9.76 29.73,9.19 C12.1
N32592: length 3
  TOP w0.5: 26.74,2.77 26.74,3.59 26.62,3.7 U3.6
N32821: length 9.3
  TOP w0.254: R6.2 22.18,9.24 24.2,9.24 24.72,9.76 27.13,9.76 27.89,10.53 27.89,11.26
N35796: length 5.4
  TOP w0.5: 26.62,11.26 26.62,12.65 27.54,13.57 28.79,13.57 29.23,14.01 C17.1
N36210: length 2.4
  TOP w0.5: C17.2 R9.2
N38494: length 17.5
  TOP w0.254: 25.36,11.26 25.36,11.99 24.72,12.63 v1(24.72,13.32) ; R8.2 R10.1 31.55,17.41 v1(32.34,16.62)
  BOTTOM w0.254: v1(24.72,13.32) 24.72,15.6 25.74,16.62 v1(32.34,16.62)
N053341: length 6.9
  TOP w0.254: R1.2 60.16,3.38 58.67,1.89 56.09,1.89 J2.4
N053344: length 6.7
  TOP w0.254: J2.3 55.84,7.22 58.93,7.22 60.16,5.98 R2.1
N066431: length 3.2
  TOP w0.254: 70.96,14.21 70.96,13.55 70.96,13.55 R3.1
N066591: length 3.2
  TOP w0.254: D2.1 49.37,28.79 49.37,28.79 R4.1
N113201: length 11
  TOP w0.5: U2.2 14.4,30.78 13.89,30.27 13.89,21.82
N288331: length 14.4
  TOP w0.5: 8.88,21.82 8.88,18.69 7.58,17.38 3.77,17.38 2.55,16.16 F1.1

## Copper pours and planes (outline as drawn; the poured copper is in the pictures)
GND on TOP, GND: 0.5,47 1.23,48.77 3,49.5 82,49.5 83.77,48.77 84.5,47 84.5,3 83.77,1.23 82,0.5 3,0.5 1.23,1.23 0.5,3
